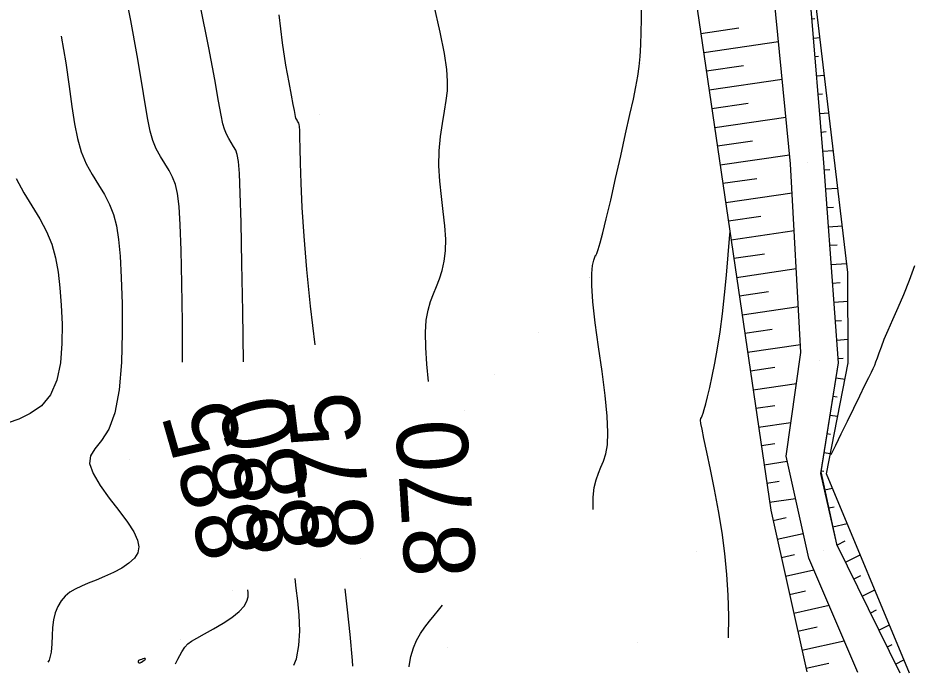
# Model space of a CAD drawing. Extents: x 400243 to 403697, y 4403637 to 4408083.
# Drawn here: x 402859.8 to 402954.4, y 4405854.6 to 4405923.8 of the extents above; entities that cross this region are included whole.
import ezdxf

# ---------------------------------------------------------------- set-up
doc = ezdxf.new("R2010")
doc.units = 0
doc.layers.add('HH_IC', color=7, linetype='Continuous')

msp = doc.modelspace()

# ---------------------------------------------------------------- linework, layer by layer
at = {"layer": 'HH_IC'}
for p, q in [((402929.379, 4405939.814), (402939.345, 4405871.783)), ((402941.426, 4405908.372), (402939.568, 4405927.469)), ((402941.426, 4405908.372), (402939.568, 4405927.469)), ((402941.426, 4405908.372), (402939.568, 4405927.469)), ((402943.342, 4405927.638), (402944.913, 4405908.491)), ((402943.342, 4405927.638), (402944.913, 4405908.491)), ((402947.491, 4405896.893), (402943.786, 4405928.193)), ((402943.993, 4405923.679), (402943.669, 4405923.652)), ((402935.974, 4405922.692), (402931.973, 4405922.106)), ((402943.833, 4405921.659), (402944.552, 4405921.718)), ((402932.263, 4405920.127), (402940.17, 4405921.285)), ((402925.732, 4405918.974), (402925.732, 4405918.974)), ((402944.392, 4405919.698), (402943.996, 4405919.666)), ((402936.458, 4405918.72), (402932.553, 4405918.148)), ((402932.843, 4405916.169), (402940.557, 4405917.299)), ((402944.16, 4405917.672), (402945.023, 4405917.743)), ((402944.791, 4405915.717), (402944.323, 4405915.679)), ((402936.942, 4405914.748), (402933.133, 4405914.19)), ((402891.68, 4405913.595), (402891.68, 4405913.595)), ((402933.423, 4405912.211), (402940.945, 4405913.313)), ((402944.487, 4405913.686), (402945.493, 4405913.768)), ((402945.19, 4405911.737), (402944.65, 4405911.692)), ((402937.426, 4405910.776), (402933.712, 4405910.233)), ((402944.814, 4405909.699), (402945.964, 4405909.793)), ((402934.002, 4405908.254), (402941.333, 4405909.328)), ((402943.22, 4405908.554), (402943.22, 4405908.554)), ((402944.913, 4405908.491), (402946.472, 4405887.348)), ((402944.913, 4405908.491), (402946.472, 4405887.348)), ((402944.913, 4405908.491), (402944.913, 4405908.491)), ((402941.426, 4405908.372), (402941.426, 4405908.372)), ((402942.535, 4405888.457), (402941.426, 4405908.372)), ((402942.535, 4405888.457), (402941.426, 4405908.372)), ((402942.535, 4405888.457), (402941.426, 4405908.372)), ((402945.586, 4405907.751), (402944.971, 4405907.705)), ((402937.888, 4405906.802), (402934.292, 4405906.275)), ((402945.118, 4405905.711), (402946.436, 4405905.808)), ((402934.582, 4405904.296), (402941.596, 4405905.323)), ((402945.968, 4405903.768), (402945.265, 4405903.716)), ((402938.29, 4405902.818), (402934.872, 4405902.317)), ((402945.412, 4405901.721), (402946.906, 4405901.832)), ((402935.162, 4405900.338), (402941.819, 4405901.313)), ((402921.378, 4405900.76), (402921.378, 4405900.76)), ((402946.35, 4405899.785), (402945.559, 4405899.727)), ((402938.691, 4405898.834), (402935.452, 4405898.359)), ((402935.742, 4405896.38), (402942.042, 4405897.303)), ((402945.706, 4405897.732), (402947.377, 4405897.856)), ((402920.189, 4405896.315), (402920.189, 4405896.315)), ((402920.233, 4405896.356), (402920.233, 4405896.356)), ((402947.491, 4405896.893), (402947.491, 4405896.893)), ((402947.529, 4405887.349), (402947.491, 4405896.893)), ((402946.674, 4405895.798), (402945.853, 4405895.738)), ((402939.093, 4405894.85), (402936.032, 4405894.401)), ((402946, 4405893.743), (402947.503, 4405893.854)), ((402936.321, 4405892.423), (402942.266, 4405893.293)), ((402946.829, 4405891.799), (402946.148, 4405891.749)), ((402914.815, 4405890.505), (402914.815, 4405890.505)), ((402939.494, 4405890.866), (402936.611, 4405890.444)), ((402946.295, 4405889.754), (402947.519, 4405889.844)), ((402936.901, 4405888.465), (402942.489, 4405889.283)), ((402940.965, 4405877.494), (402942.535, 4405888.457)), ((402940.965, 4405877.494), (402942.535, 4405888.457)), ((402940.965, 4405877.494), (402942.535, 4405888.457)), ((402942.535, 4405888.457), (402942.535, 4405888.457)), ((402946.985, 4405887.799), (402946.442, 4405887.759)), ((402939.776, 4405886.865), (402937.191, 4405886.486)), ((402944.535, 4405887.633), (402944.535, 4405887.633)), ((402946.472, 4405887.348), (402944.605, 4405875.658)), ((402946.472, 4405887.348), (402944.642, 4405875.837)), ((402945.22, 4405875.61), (402947.529, 4405887.349)), ((402946.472, 4405887.348), (402946.472, 4405887.348)), ((402947.648, 4405887.293), (402947.648, 4405887.293)), ((402910.171, 4405886.154), (402910.171, 4405886.154)), ((402946.223, 4405885.78), (402947.19, 4405885.626)), ((402937.481, 4405884.507), (402942.066, 4405885.179)), ((402941.655, 4405885.558), (402941.655, 4405885.558)), ((402946.356, 4405883.734), (402945.909, 4405883.805)), ((402906.999, 4405882.367), (402906.999, 4405882.367)), ((402939.77, 4405882.821), (402937.771, 4405882.528)), ((402938.061, 4405880.549), (402941.474, 4405881.049)), ((402945.595, 4405881.83), (402946.418, 4405881.699)), ((402906.412, 4405880.135), (402906.412, 4405880.135)), ((402945.656, 4405879.795), (402945.281, 4405879.855)), ((402939.765, 4405878.778), (402938.351, 4405878.57)), ((402940.965, 4405877.494), (402940.965, 4405877.494)), ((402943.364, 4405866.725), (402940.965, 4405877.494)), ((402943.364, 4405866.725), (402940.965, 4405877.494)), ((402943.364, 4405866.725), (402940.965, 4405877.494)), ((402944.967, 4405877.879), (402945.645, 4405877.772)), ((402871.66, 4405877.182), (402871.66, 4405877.182)), ((402938.641, 4405876.592), (402941.086, 4405876.95)), ((402944.605, 4405875.658), (402946.294, 4405868.206)), ((402944.642, 4405875.837), (402944.642, 4405875.837)), ((402944.642, 4405875.837), (402946.294, 4405868.206)), ((402944.956, 4405875.856), (402944.653, 4405875.904)), ((402953.992, 4405854.578), (402945.22, 4405875.61)), ((402945.3, 4405875.592), (402945.3, 4405875.592)), ((402900.419, 4405874.594), (402900.419, 4405874.594)), ((402940.226, 4405874.803), (402938.93, 4405874.613)), ((402945.051, 4405873.949), (402945.841, 4405874.12)), ((402939.22, 4405872.634), (402941.958, 4405873.035)), ((402939.345, 4405871.783), (402939.345, 4405871.783)), ((402939.345, 4405871.783), (402943.153, 4405854.716)), ((402946.049, 4405872.119), (402945.474, 4405871.994)), ((402886.311, 4405871.285), (402886.311, 4405871.285)), ((402940.971, 4405870.978), (402939.593, 4405870.67)), ((402945.897, 4405870.039), (402947.407, 4405870.366)), ((402940.029, 4405868.718), (402942.783, 4405869.333)), ((402891.998, 4405868.351), (402891.998, 4405868.351)), ((402946.294, 4405868.206), (402946.294, 4405868.206)), ((402946.294, 4405868.206), (402952.984, 4405854.591)), ((402946.294, 4405868.206), (402952.984, 4405854.591)), ((402947.181, 4405868.503), (402946.349, 4405868.095)), ((402931.513, 4405867.455), (402931.513, 4405867.455)), ((402941.841, 4405867.073), (402940.464, 4405866.766)), ((402944.889, 4405867.558), (402944.889, 4405867.558)), ((402947.231, 4405866.3), (402948.785, 4405867.063)), ((402896.012, 4405866.705), (402896.012, 4405866.705)), ((402943.364, 4405866.725), (402943.364, 4405866.725)), ((402948.537, 4405854.648), (402943.364, 4405866.725)), ((402948.537, 4405854.648), (402943.364, 4405866.725)), ((402948.537, 4405854.648), (402943.364, 4405866.725)), ((402940.9, 4405864.814), (402943.896, 4405865.483)), ((402948.834, 4405864.859), (402948.113, 4405864.505)), ((402882.486, 4405863.311), (402882.486, 4405863.311)), ((402943.016, 4405863.237), (402941.335, 4405862.862)), ((402948.995, 4405862.71), (402950.327, 4405863.364)), ((402941.771, 4405860.91), (402945.499, 4405861.742)), ((402950.488, 4405861.215), (402949.877, 4405860.914)), ((402944.253, 4405859.415), (402942.206, 4405858.958)), ((402950.759, 4405859.119), (402951.87, 4405859.666)), ((402877.018, 4405858.158), (402877.018, 4405858.158)), ((402925.308, 4405857.789), (402925.308, 4405857.789)), ((402942.642, 4405857.006), (402947.101, 4405858.001)), ((402952.141, 4405857.57), (402951.641, 4405857.324)), ((402905.194, 4405857.293), (402905.194, 4405857.293)), ((402872.729, 4405855.771), (402872.729, 4405855.771)), ((402945.49, 4405855.592), (402943.078, 4405855.054)), ((402952.523, 4405855.529), (402953.413, 4405855.967))]:
    msp.add_line(p, q, dxfattribs=at)
for points in [[(402877.205, 4405887.428), (402877.21, 4405891.644), (402877.152, 4405895.722), (402877.062, 4405899.257), (402876.963, 4405901.943), (402876.844, 4405903.868), (402876.685, 4405905.219), (402876.466, 4405906.181), (402876.169, 4405906.943), (402875.784, 4405907.663), (402875.341, 4405908.389), (402874.881, 4405909.144), (402874.444, 4405909.949), (402874.073, 4405910.826), (402873.789, 4405911.818), (402873.546, 4405913.059), (402873.282, 4405914.703), (402872.931, 4405916.906), (402872.431, 4405919.823), (402871.741, 4405923.521), (402870.917, 4405927.715)], [(402883.648, 4405887.464), (402883.575, 4405892.777), (402883.485, 4405897.858), (402883.393, 4405902.163), (402883.309, 4405905.282), (402883.225, 4405907.342), (402883.126, 4405908.607), (402882.998, 4405909.338), (402882.828, 4405909.799), (402882.608, 4405910.209), (402882.355, 4405910.624), (402882.093, 4405911.055), (402881.844, 4405911.514), (402881.631, 4405912.015), (402881.464, 4405912.609), (402881.285, 4405913.511), (402881.026, 4405914.978), (402880.615, 4405917.263), (402879.981, 4405920.623), (402879.086, 4405925.178)], [(402903.197, 4405885.368), (402903.034, 4405887.197), (402902.914, 4405888.97), (402902.879, 4405890.558), (402902.962, 4405891.865), (402903.148, 4405892.93), (402903.407, 4405893.826), (402903.712, 4405894.625), (402904.036, 4405895.399), (402904.351, 4405896.213), (402904.632, 4405897.097), (402904.853, 4405898.077), (402904.99, 4405899.175), (402905.018, 4405900.415), (402904.925, 4405901.81), (402904.752, 4405903.326), (402904.553, 4405904.921), (402904.384, 4405906.551), (402904.298, 4405908.172), (402904.334, 4405909.745), (402904.468, 4405911.242), (402904.66, 4405912.643), (402904.87, 4405913.923), (402905.058, 4405915.06), (402905.185, 4405916.067), (402905.217, 4405917.1), (402905.122, 4405918.35), (402904.868, 4405920.007), (402904.421, 4405922.264), (402903.769, 4405925.238)], [(402920.585, 4405871.849), (402920.592, 4405873.147), (402920.702, 4405874.176), (402920.891, 4405875.006), (402921.133, 4405875.704), (402921.402, 4405876.337), (402921.673, 4405876.98), (402921.911, 4405877.732), (402922.082, 4405878.699), (402922.15, 4405879.989), (402922.08, 4405881.706), (402921.854, 4405883.904), (402921.522, 4405886.423), (402921.15, 4405889.05), (402920.804, 4405891.574), (402920.553, 4405893.78), (402920.443, 4405895.505), (402920.451, 4405896.77), (402920.532, 4405897.647), (402920.645, 4405898.206), (402920.746, 4405898.518), (402920.802, 4405898.652), (402920.823, 4405898.673), (402920.83, 4405898.644), (402920.843, 4405898.628), (402920.882, 4405898.689), (402920.966, 4405898.892), (402921.106, 4405899.309), (402921.315, 4405900.012), (402921.6, 4405901.077), (402921.974, 4405902.575), (402922.438, 4405904.536), (402922.96, 4405906.81), (402923.5, 4405909.204), (402924.017, 4405911.523), (402924.471, 4405913.572), (402924.83, 4405915.212), (402925.101, 4405916.518), (402925.3, 4405917.619), (402925.442, 4405918.644), (402925.543, 4405919.723), (402925.615, 4405920.949), (402925.663, 4405922.273), (402925.685, 4405923.608), (402925.683, 4405924.87)], [(402891.205, 4405889.24), (402890.74, 4405893.318), (402890.341, 4405897.217), (402890.05, 4405900.714), (402889.858, 4405903.757), (402889.74, 4405906.333), (402889.675, 4405908.43), (402889.639, 4405910.039), (402889.612, 4405911.165), (402889.588, 4405911.889), (402889.561, 4405912.313), (402889.529, 4405912.534), (402889.487, 4405912.654), (402889.432, 4405912.756), (402889.369, 4405912.859), (402889.304, 4405912.966), (402889.243, 4405913.079), (402889.19, 4405913.203), (402889.148, 4405913.353), (402889.101, 4405913.592), (402889.028, 4405913.997), (402888.909, 4405914.644), (402888.725, 4405915.61), (402888.462, 4405916.97), (402888.141, 4405918.795), (402887.787, 4405921.151), (402887.43, 4405924.109)], [(402864.397, 4405921.865), (402864.881, 4405919.023), (402865.247, 4405916.548), (402865.537, 4405914.428), (402865.807, 4405912.606), (402866.114, 4405911.028), (402866.514, 4405909.638), (402867.045, 4405908.384), (402867.669, 4405907.234), (402868.326, 4405906.154), (402868.96, 4405905.116), (402869.51, 4405904.087), (402869.935, 4405903.025), (402870.244, 4405901.831), (402870.462, 4405900.394), (402870.616, 4405898.605), (402870.731, 4405896.351), (402870.819, 4405893.586), (402870.846, 4405890.511), (402870.763, 4405887.392), (402870.523, 4405884.493), (402870.079, 4405882.08), (402869.418, 4405880.339), (402868.661, 4405879.141), (402867.966, 4405878.277), (402867.49, 4405877.539), (402867.388, 4405876.719), (402867.765, 4405875.659), (402868.514, 4405874.409), (402869.475, 4405873.069), (402870.489, 4405871.74), (402871.395, 4405870.521), (402872.062, 4405869.489), (402872.466, 4405868.631), (402872.612, 4405867.909), (402872.504, 4405867.283), (402872.147, 4405866.717), (402871.555, 4405866.179), (402870.785, 4405865.671), (402869.904, 4405865.198), (402868.981, 4405864.768), (402868.081, 4405864.389), (402867.261, 4405864.061), (402866.529, 4405863.76), (402865.88, 4405863.454), (402865.309, 4405863.112), (402864.814, 4405862.702), (402864.39, 4405862.201), (402864.039, 4405861.61), (402863.766, 4405860.939), (402863.573, 4405860.197), (402863.464, 4405859.395), (402863.428, 4405858.543), (402863.406, 4405857.665), (402863.325, 4405856.789), (402863.112, 4405855.941), (402863.002, 4405855.731)], [(402859.646, 4405906.819), (402860.457, 4405905.323), (402861.312, 4405903.92), (402862.135, 4405902.569), (402862.852, 4405901.232), (402863.403, 4405899.868), (402863.803, 4405898.443), (402864.081, 4405896.92), (402864.27, 4405895.266), (402864.4, 4405893.445), (402864.486, 4405891.45), (402864.481, 4405889.378), (402864.32, 4405887.355), (402863.94, 4405885.508), (402863.277, 4405883.96), (402862.302, 4405882.803), (402861.13, 4405881.985), (402859.911, 4405881.416), (402858.793, 4405881.01)], [(402934.882, 4405858.296), (402934.907, 4405860.58), (402934.853, 4405862.802), (402934.717, 4405864.997), (402934.501, 4405867.198), (402934.202, 4405869.44), (402933.828, 4405871.731), (402933.411, 4405873.982), (402932.989, 4405876.079), (402932.604, 4405877.908), (402932.292, 4405879.355), (402932.085, 4405880.343), (402931.973, 4405880.947), (402931.936, 4405881.28), (402931.955, 4405881.453), (402932.011, 4405881.579), (402932.089, 4405881.757), (402932.19, 4405882.032), (402932.317, 4405882.437), (402932.476, 4405883.003), (402932.672, 4405883.764), (402932.906, 4405884.744), (402933.168, 4405885.935), (402933.444, 4405887.323), (402933.722, 4405888.894), (402933.989, 4405890.633), (402934.233, 4405892.523), (402934.456, 4405894.53), (402934.66, 4405896.62), (402934.849, 4405898.756), (402935.026, 4405900.903), (402935.045, 4405901.138)], [(402945.717, 4405877.669), (402946.216, 4405878.656), (402946.796, 4405879.833), (402947.45, 4405881.179), (402948.121, 4405882.567), (402948.754, 4405883.876), (402949.291, 4405884.98), (402949.691, 4405885.791), (402949.973, 4405886.358), (402950.172, 4405886.766), (402950.32, 4405887.098), (402950.453, 4405887.44), (402950.601, 4405887.864), (402950.785, 4405888.398), (402951.024, 4405889.056), (402951.334, 4405889.855), (402951.734, 4405890.809), (402952.232, 4405891.928), (402952.799, 4405893.195), (402953.4, 4405894.584), (402953.995, 4405896.071), (402954.547, 4405897.634)], [(402888.961, 4405855.402), (402889.251, 4405856.076), (402889.514, 4405857.48), (402889.586, 4405859.058), (402889.525, 4405860.682), (402889.388, 4405862.224), (402889.231, 4405863.556), (402889.097, 4405864.584)], [(402876.469, 4405855.561), (402876.728, 4405856.053), (402877.135, 4405856.814), (402877.449, 4405857.321), (402877.76, 4405857.668), (402878.156, 4405857.955), (402878.727, 4405858.278), (402879.53, 4405858.711), (402880.489, 4405859.243), (402881.493, 4405859.837), (402882.434, 4405860.459), (402883.203, 4405861.073), (402883.717, 4405861.65), (402884.009, 4405862.175), (402884.134, 4405862.643), (402884.153, 4405863.044), (402884.122, 4405863.37)], [(402895.2, 4405855.323), (402895.167, 4405855.924), (402894.926, 4405858.664), (402894.645, 4405861.268), (402894.383, 4405863.474)], [(402901.158, 4405855.248), (402901.162, 4405855.303), (402901.337, 4405856.346), (402901.596, 4405857.239), (402901.934, 4405858.03), (402902.343, 4405858.76), (402902.804, 4405859.441), (402903.292, 4405860.077), (402903.783, 4405860.67), (402904.253, 4405861.225), (402904.677, 4405861.755)], [(402872.751, 4405855.678), (402872.881, 4405855.742), (402873.027, 4405855.835), (402873.162, 4405855.937), (402873.261, 4405856.03), (402873.297, 4405856.096), (402873.255, 4405856.119), (402873.151, 4405856.107), (402873.012, 4405856.072), (402872.864, 4405856.024), (402872.732, 4405855.977), (402872.638, 4405855.939), (402872.579, 4405855.91), (402872.547, 4405855.89), (402872.532, 4405855.876), (402872.527, 4405855.866), (402872.524, 4405855.86), (402872.524, 4405855.852), (402872.524, 4405855.841), (402872.527, 4405855.822), (402872.532, 4405855.792), (402872.54, 4405855.749), (402872.558, 4405855.704), (402872.594, 4405855.669), (402872.656, 4405855.656), (402872.751, 4405855.678)]]:
    msp.add_lwpolyline(points, dxfattribs=at)

# ---------------------------------------------------------------- texts
for s, rotation, p in [('875', 97.03197, (402897.606, 4405867.977)), ('885', 106.04047, (402886.729, 4405867.876)), ('880', 103.39599, (402892.084, 4405868.229)), ('870', 93.58825, (402908.237, 4405864.907))]:
    msp.add_text(s, height=7.5, rotation=rotation, dxfattribs=at).set_placement(p)

doc.saveas('drawing.dxf')
